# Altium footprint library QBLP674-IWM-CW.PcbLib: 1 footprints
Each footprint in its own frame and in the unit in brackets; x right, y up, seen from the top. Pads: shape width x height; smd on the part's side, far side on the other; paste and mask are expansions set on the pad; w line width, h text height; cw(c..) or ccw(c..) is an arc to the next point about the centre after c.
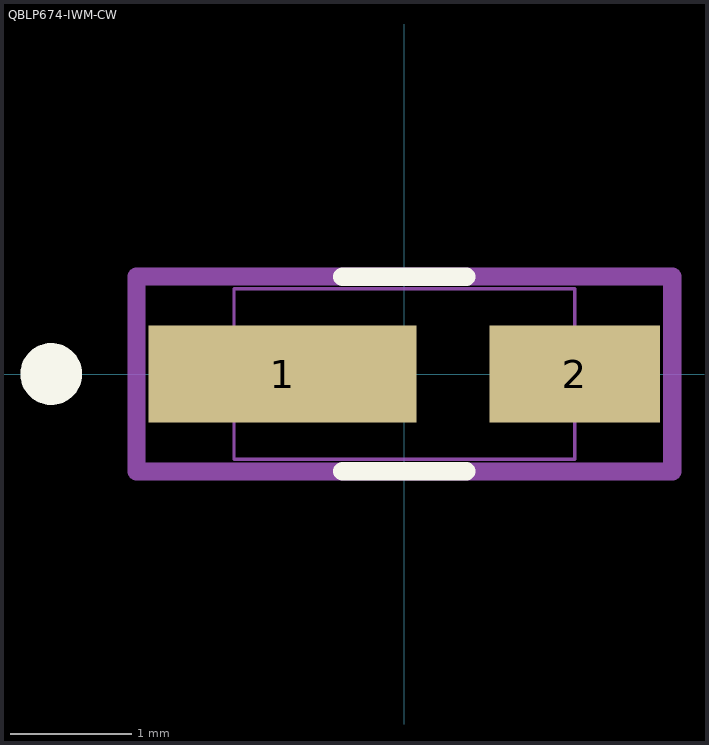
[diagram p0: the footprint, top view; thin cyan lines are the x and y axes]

## QBLP674-IWM-CW [mm]
pads (2):
  rect 2.2x0.8 smd paste+0 mask+0: 1(-1,0)
  rect 1.4x0.8 smd paste+0 mask+0: 2(1.4,0)
Top Overlay:
  circle w0.254: c-2.9,0 r0.127
  lines w0.152: -0.508,-0.8 0.508,-0.8 ; -0.508,0.8 0.508,0.8
Mechanical 5:
  lines w0.15: -2.2,-0.8 2.2,-0.8 2.2,0.8 -2.2,0.8 -2.2,-0.8
Mechanical 13:
  lines w0.025: -1.4,-0.35 -1.5,-0.35 -1.5,0.35 -1.4,0.35 ; 1.4,-0.35 1.5,-0.35 1.5,0.35 1.4,0.35 ; -1.4,-0.7 -1.4,0.7 1.4,0.7 1.4,-0.7 -1.4,-0.7
Mechanical 15:
  lines w0.15: -2.2,-0.8 -2.2,0.8 2.2,0.8 2.2,-0.8 -2.2,-0.8
3D body "QBLP674.step": height 0.75, standoff 0, extent -1.522,-0.7 1.478,0.7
